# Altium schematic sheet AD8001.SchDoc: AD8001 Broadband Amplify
size A4; Organization: POSTS&TELECOMMUNICATIONS PRESS; Address1: SiChuan; Address2: Cheng Du; Address3: SiChuan University; Revision: 1.0; SheetNumber: 1; SheetTotal: 1
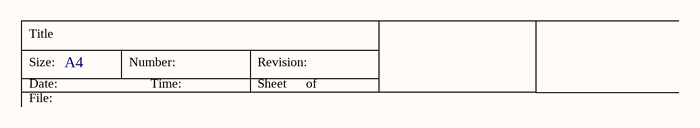
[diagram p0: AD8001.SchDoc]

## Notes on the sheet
- Title
- Size:
- Date:
- A4
- Number:
- Time:
- Revision:
- Sheet
- of
- File:
